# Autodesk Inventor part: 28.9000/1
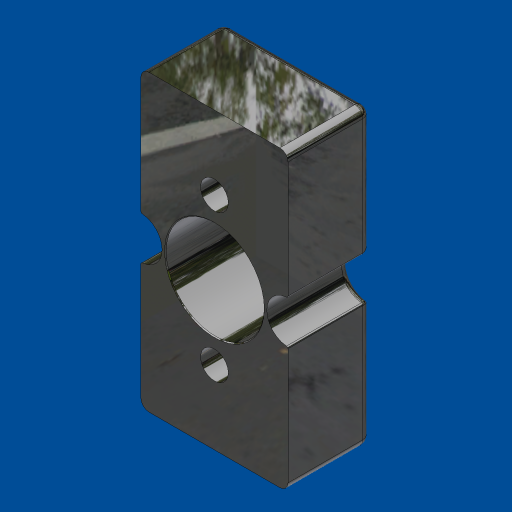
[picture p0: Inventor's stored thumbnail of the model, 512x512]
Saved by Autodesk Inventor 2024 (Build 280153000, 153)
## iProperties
Created: 2022-07
Part Number: 28.9000/1
Material: Aluminum 6061
Document SubType Name: Modeling
Designer: amoles
Density: 2.7 g/cm^3
Appearance: Anodized - Light Gray
Stock Number: 20.9473 1.25" X 2" AL BSTOCK
Description: ROTATIONAL ELEMENT BEARING PLATE
Mass: 211.255 g
Surface Area: 173.148 cm^2
Volume: 78.2426 cm^3
FINISH: ETCH & CLEAR ANODIZE
Author: amoles
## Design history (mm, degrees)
sketch "Sketch1"
  geometry: L1 (-22.5, 45)-(22.5, 45); L2 (22.5, 45)-(22.5, -45); L3 (22.5, -45)-(-22.5, -45); L4 (-22.5, -45)-(-22.5, 45); 3 further points
  constraints: 8 end point, 2 midpoint, 2 parallel, 1 horizontal, 1 horizontal alignment, 1 perpendicular, 1 vertical alignment
  dimensions: "d0" = 45 distance of L1.start L1.end; "d1" = 90 distance of L3.end L1.start
extrude "Extrusion1" new body sketch "Sketch1" distance "d2" = 25.4; taper "d3" = 0 deg
sketch "Sketch2"
  geometry: C1 r 12 at (0, 0); 1 further point
  constraints: 1 centre point, 1 coincident
  dimensions: "d4" = 24 diameter of C1
extrude "Extrusion2" cut sketch "Sketch2" extent not by distance; stored distance "d5" = 0; taper "d6" = 0 deg
sketch "Sketch3"
  geometry: C1 r 12 at (0, 0) reference; C2 r 12 at (0, 0) reference; C3 r 15 at (0, 0)
  constraints: 1 centre point, 1 coincident
  dimensions: "d7" = 30 diameter of C3
extrude "Extrusion3" cut sketch "Sketch3" distance "d8" = 21.844; taper "d9" = 0 deg
sketch "Sketch4"
  geometry: C1 r 12 at (0, 0) reference; 2 further points
  constraints: 2 vertical alignment
  dimensions: "d28" = 22.5 distance of point (0, 22.5) C1.centre; "d29" = 22.5 distance of point (0, -22.5) C1.centre
hole "Hole1" sketch "Sketch4" diameter "d12" = 8.5; stored, may be unused: countersink angle "d16" = 82 deg, drill point angle "d18" = 118 deg; dims "d13" = 19.05, "d14" = 13, "d15" = 5.334, "d17" = 25.4
fillet "Fillet1" dims "d37" = 2.4892
sketch "Sketch6"
  geometry: L1 (22.5, -42.511)-(22.5, 42.511) reference; L2 (-22.5, 42.511)-(-22.5, -42.511) reference; C1 r 15 at (0, 0) reference; C2 r 6.5 at (22.5, 0); C3 r 6.5 at (-22.5, 0); 4 further points
  constraints: 2 centre point, 2 horizontal alignment, 1 equal radius
  dimensions: "d39" = 13 diameter of C2; "d40" = 45 distance of C3.centre C2.centre; "d41" = 22.5 distance of C2.centre C1.centre (= 0.5 x d40)
extrude "Extrusion4" cut sketch "Sketch6" extent not by distance; stored distance "d42" = 21.844; taper "d43" = 0 deg
fillet "Fillet3" dims "d44" = 0.5
fillet "Fillet4" dims "d45" = 2.5
chamfer "Chamfer4" distance "d46" = 0.254; stored, may be unused: second distance "d47" = 3.175, angle "d48" = 45 deg
body "Solid1"
